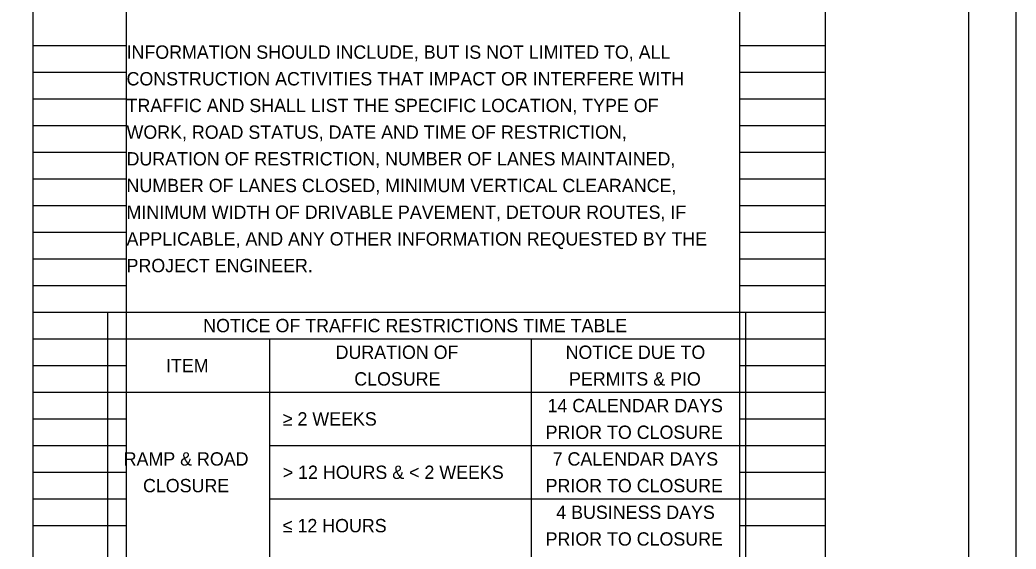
# Model space of a CAD drawing. Extents: x 0 to 34, y 0 to 22.
# Drawn here: x 23.54 to 34, y 5.49 to 11.05 of the extents above; entities that cross this region are included whole.
import ezdxf

# ---------------------------------------------------------------- set-up
doc = ezdxf.new("R2010")
doc.units = 0
for name, color, linetype in [('SH_Border', 7, 'Continuous'), ('SH_Cut_Line', 7, 'Continuous'), ('SH_Data', 7, 'Continuous'), ('SH_Text', 7, 'Continuous')]:
    doc.layers.add(name, color=color, linetype=linetype)

msp = doc.modelspace()

# ---------------------------------------------------------------- linework, layer by layer
at = {"layer": 'SH_Border'}
msp.add_line((32, 0.5), (32, 21.5), dxfattribs=at)
msp.add_lwpolyline([(1.5, 21.5), (33.5, 21.5), (33.5, 0.5), (1.5, 0.5)], close=True, dxfattribs=at)
at = {"layer": 'SH_Cut_Line'}
msp.add_lwpolyline([(0, 0), (34, 0), (34, 22), (0, 22)], close=True, dxfattribs=at)
at = {"layer": 'SH_Data'}
for p, q in [((23.68, 0.98), (23.68, 21.14)), ((24.66, 0.98), (24.66, 21.14)), ((31.1, 0.98), (31.1, 21.14)), ((32, 0.98), (32, 21.14)), ((23.68, 10.78), (24.66, 10.78)), ((31.1, 10.78), (32, 10.78)), ((23.68, 10.5), (24.66, 10.5)), ((31.1, 10.5), (32, 10.5)), ((23.68, 10.22), (24.66, 10.22)), ((31.1, 10.22), (32, 10.22)), ((23.68, 9.94), (24.66, 9.94)), ((31.1, 9.94), (32, 9.94)), ((23.68, 9.66), (24.66, 9.66)), ((31.1, 9.66), (32, 9.66)), ((23.68, 9.38), (24.66, 9.38)), ((31.1, 9.38), (32, 9.38)), ((23.68, 9.1), (24.66, 9.1)), ((31.1, 9.1), (32, 9.1)), ((23.68, 8.82), (24.66, 8.82)), ((31.1, 8.82), (32, 8.82)), ((23.68, 8.54), (24.66, 8.54)), ((31.1, 8.54), (32, 8.54)), ((23.68, 8.26), (24.66, 8.26)), ((31.1, 8.26), (32, 8.26)), ((23.68, 7.98), (24.66, 7.98)), ((24.46, 7.98), (24.46, 2.66)), ((24.46, 7.98), (31.16, 7.98)), ((31.1, 7.98), (32, 7.98)), ((31.16, 7.98), (31.16, 2.66)), ((23.68, 7.7), (24.66, 7.7)), ((24.46, 7.7), (31.16, 7.7)), ((26.16, 7.7), (26.16, 2.66)), ((28.91, 7.7), (28.91, 2.66)), ((31.1, 7.7), (32, 7.7)), ((23.68, 7.42), (24.66, 7.42)), ((31.1, 7.42), (32, 7.42)), ((23.68, 7.14), (24.66, 7.14)), ((24.46, 7.14), (31.16, 7.14)), ((31.1, 7.14), (32, 7.14)), ((23.68, 6.86), (24.66, 6.86)), ((31.1, 6.86), (32, 6.86)), ((23.68, 6.58), (24.66, 6.58)), ((26.16, 6.58), (31.16, 6.58)), ((31.1, 6.58), (32, 6.58)), ((23.68, 6.3), (24.66, 6.3)), ((31.1, 6.3), (32, 6.3)), ((23.68, 6.02), (24.66, 6.02)), ((26.16, 6.02), (31.16, 6.02)), ((31.1, 6.02), (32, 6.02)), ((23.68, 5.74), (24.66, 5.74)), ((31.1, 5.74), (32, 5.74))]:
    msp.add_line(p, q, dxfattribs=at)

# ---------------------------------------------------------------- texts
for s, p in [('NOTICE OF TRAFFIC RESTRICTIONS TIME TABLE', (25.465, 7.77)), ('DURATION OF', (26.855, 7.49)), ('NOTICE DUE TO', (29.27, 7.49)), ('ITEM', (25.074, 7.35)), ('CLOSURE', (27.051, 7.21)), ('PERMITS & PIO', (29.306, 7.21)), ('RAMP & ROAD', (24.63, 6.37)), ('CLOSURE', (24.833, 6.09))]:
    msp.add_text(s, height=0.14, dxfattribs=at).set_placement(p)
at = {"layer": 'SH_Text'}
for s, p in [('INFORMATION SHOULD INCLUDE, BUT IS NOT LIMITED TO, ALL ', (24.66, 10.64)), ('CONSTRUCTION ACTIVITIES THAT IMPACT OR INTERFERE WITH ', (24.66, 10.36)), ('TRAFFIC AND SHALL LIST THE SPECIFIC LOCATION, TYPE OF ', (24.66, 10.08)), ('WORK, ROAD STATUS, DATE AND TIME OF RESTRICTION, ', (24.66, 9.8)), ('DURATION OF RESTRICTION, NUMBER OF LANES MAINTAINED, ', (24.66, 9.52)), ('NUMBER OF LANES CLOSED, MINIMUM VERTICAL CLEARANCE, ', (24.66, 9.24)), ('MINIMUM WIDTH OF DRIVABLE PAVEMENT, DETOUR ROUTES, IF ', (24.66, 8.96)), ('APPLICABLE, AND ANY OTHER INFORMATION REQUESTED BY THE ', (24.66, 8.68)), ('PROJECT ENGINEER.', (24.66, 8.4)), ('14 CALENDAR DAYS', (29.08, 6.93)), ('≥ 2 WEEKS', (26.3, 6.79)), ('PRIOR TO CLOSURE', (29.06, 6.65)), ('7 CALENDAR DAYS', (29.134, 6.37)), ('> 12 HOURS & < 2 WEEKS', (26.3, 6.23)), ('PRIOR TO CLOSURE', (29.06, 6.09)), ('4 BUSINESS DAYS', (29.172, 5.81)), ('≤ 12 HOURS', (26.3, 5.67)), ('PRIOR TO CLOSURE', (29.06, 5.53))]:
    msp.add_text(s, height=0.14, dxfattribs=at).set_placement(p)

doc.saveas('drawing.dxf')
